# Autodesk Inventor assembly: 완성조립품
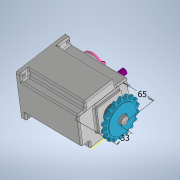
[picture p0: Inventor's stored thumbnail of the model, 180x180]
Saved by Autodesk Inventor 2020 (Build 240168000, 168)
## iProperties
Created: 2022-01
Part Number: 완성조립품
Document SubType Name: Assembly
Designer: user
Author: user
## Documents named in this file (16)
- C:\Users\user\Desktop\720112V1016\완성조립품.iam
- C:\Users\user\Desktop\720112V1016\멈춤나사 M3.ipt
- C:\Users\user\Desktop\720112V1016\메인 축.ipt
- C:\Users\user\Desktop\720112V1016\베어링 608.ipt
- C:\Users\user\Desktop\720112V1016\베어링 6003.ipt
- C:\Users\user\Desktop\720112V1016\본체.ipt
- C:\Users\user\Desktop\720112V1016\볼트 M4 x 10.ipt
- C:\Users\user\Desktop\720112V1016\부시.ipt
- C:\Users\user\Desktop\720112V1016\상부 캡.ipt
- C:\Users\user\Desktop\720112V1016\서브 축.ipt
- C:\Users\user\Desktop\720112V1016\스프로킷.ipt
- C:\Users\user\Desktop\720112V1016\슬라이더.ipt
- C:\Users\user\Desktop\720112V1016\오일 실 8 x 22 x 7.ipt
- C:\Users\user\Desktop\720112V1016\오일 실 17 x 32 x 8.ipt
- C:\Users\user\Desktop\720112V1016\커버.ipt
- C:\Users\user\Desktop\720112V1016\키 5 x 5.ipt
